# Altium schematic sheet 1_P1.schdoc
size 309 x 223 mm; Symbol: Sheet-Symbol_A4; Device: Sheet-Symbol_A4; Company: 嘉立创EDA; Version: V1.0; Page Size: A4; @Project Name: 辉光管_2024.2.16; @Page Count: 1; @Update Date: 2024-05-18; @Create Date: 2024-05-18; @Schematic Name: Schematic5; @Page No: 1; @Page Name: P1
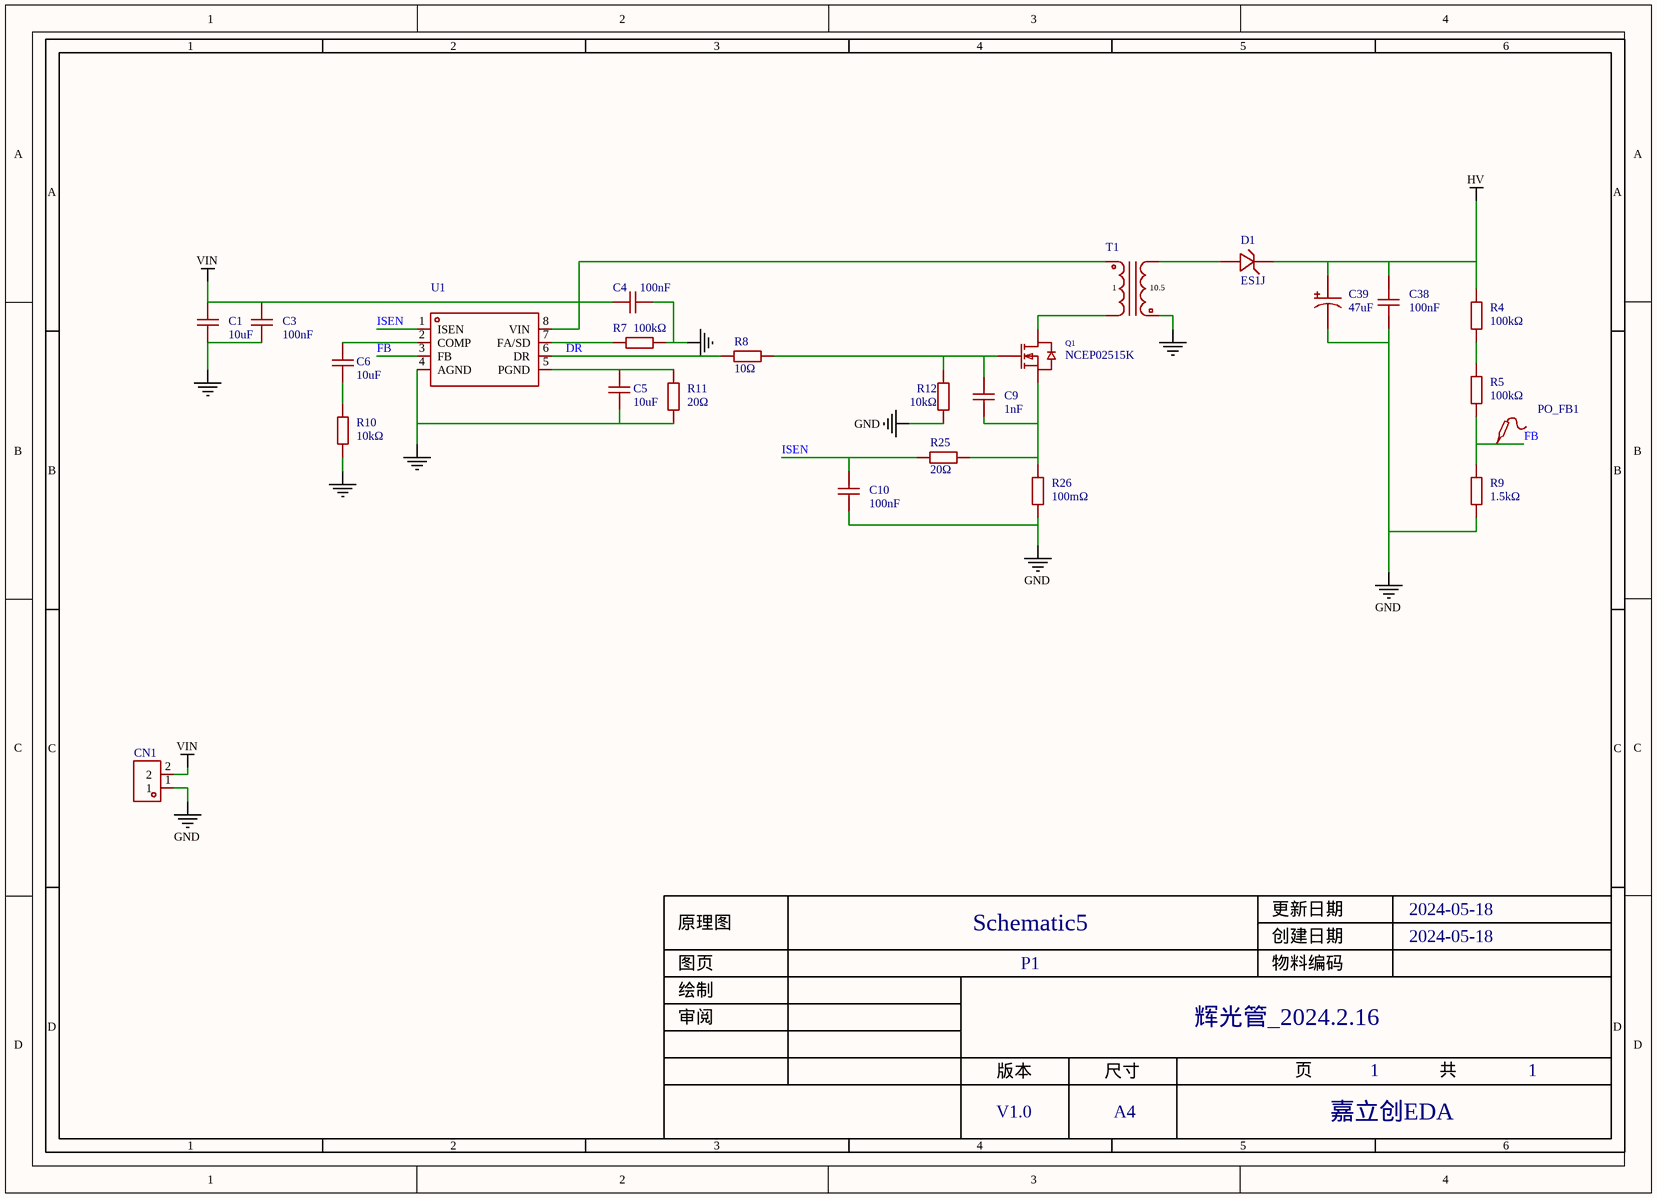
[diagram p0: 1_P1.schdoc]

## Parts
C1  10uF  [C0805]  (value not drawn)
C3  100nF  [C0603]  (value not drawn)
C4  100nF  [C0603]  (value not drawn)
C5  10uF  [C0805]  (value not drawn)
C6  10uF  [C0805]  (value not drawn)
C9  1nF  [C0603]  (value not drawn)
C10  100nF  [C0603]  (value not drawn)
C38  100nF  [C1206]  (value not drawn)
C39  47uF  [CAP-TH_BD12.5-P5.00-D0.6-FD]  (value not drawn)
CN1  ZX-XH2.54-2PZZ  [CONN-TH_2P-P2.50_HX25003-2A]  (value not drawn)
D1  ES1J  [SMA_L4.4-W2.8-LS5.4-RD]  (value not drawn)
PO_FB1  Test-Point  [Test-Point-0.5mm]  (value not drawn)
Q1  NCEP02515K  [TO-252-3_L6.6-W6.1-P4.58-LS10.1-BR-2]  (value not drawn)
R4  100kΩ  [R1206]  (value not drawn)
R5  100kΩ  [R1206]  (value not drawn)
R7  100kΩ  [R0603]  (value not drawn)
R8  10Ω  [R0603]  (value not drawn)
R9  1.5kΩ  [R0805]  (value not drawn)
R10  10kΩ  [R0603]  (value not drawn)
R11  20Ω  [R0603]  (value not drawn)
R12  10kΩ  [R0603]  (value not drawn)
R25  20Ω  [R0603]  (value not drawn)
R26  100mΩ  [R1206]  (value not drawn)
T1  TTRN-060S-013-T  [TTRN-060S-013]  (value not drawn)
U1  SiLM6478-AQ/Boost升压芯片  [MSOP-8_L3.0-W3.0-P0.65-LS4.9-TL]  (value not drawn)

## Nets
GND: C1.1 C3.1 C4.1 C5.1 C10.1 C38.1 C39.2 CN1.1 R7.1 R9.1 R10.1 R11.1 R12.1 R26.1 T1.3 U1.4(AGND)
HV: C38.2 C39.1 D1.1(C) R4.1
VIN: C1.2 C3.2 C4.2 CN1.2 T1.1 U1.8(VIN)
DR: R8.1 U1.6(DR)
FB: PO_FB1.1 R5.2 R9.2 U1.3(FB)
ISEN: C10.2 R25.1 U1.1(ISEN)
NetC5_2: C5.2 R11.2 U1.5(PGND)
NetC6_1: C6.1 R10.2
NetC6_2: C6.2 U1.2(COMP)
NetC9_1: C9.1 Q1.3(S) R25.2 R26.2
NetC9_2: C9.2 Q1.1(G) R8.2 R12.2
NetD1_2: D1.2(A) T1.2
NetQ1_2: Q1.2(D) T1.5
NetR4_2: R4.2 R5.1
NetR7_2: R7.2 U1.7(FA/SD)

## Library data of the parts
C1 C5 C6 = 0805X106K250NT: 容值:10uF;精度:±10%;额定电压:25V;材质(温度系数):X5R;; Manufacturer: FH(风华); Add into BOM: yes; Tolerance: ±10%; Voltage Rated: 25V; Temperature Coefficient: X5R
C3 C4 C10 = 0603B104K500NT: 容值:100nF;精度:±10%;额定电压:50V;材质(温度系数):X7R;; Manufacturer: FH(风华); Add into BOM: yes; Tolerance: ±10%; Voltage Rated: 50V; Temperature Coefficient: X7R
C9 = CC0603KRX7R9BB102: 容值:1nF;精度:±10%;额定电压:50V;材质(温度系数):X7R;; Manufacturer: YAGEO(国巨); Add into BOM: yes; Tolerance: ±10%; Voltage Rated: 50V; Temperature Coefficient: X7R
C38 = 1206B104K251NT_C2909525: 容值:100nF;精度:±10%;额定电压:250V;材质(温度系数):X7R;; Manufacturer: FH(风华); Add into BOM: yes; Tolerance: ±10%; Voltage Rated: 250V; Temperature Coefficient: X7R
C39 = EGS2EM470W16OT: 容值:47uF;精度:±20%;额定电压:250V;纹波电流:-;等效串联电阻:-;; Manufacturer: AISHI(艾华集团); Add into BOM: yes; Tolerance: ±20%; Rated Voltage: 250V; φD: 12.5mm; L: 16mm; Lifetime @ Temp: 6000hrs@105℃
CN1 = ZX-XH2.54-2PZZ: 插针结构:1x2P;间距:2.54mm;安装方式:直插;参考系列:XH;总PIN数:2P;排数:1;每排PIN数:2;行距:-;额定电流:3A;触头材质:黄铜;触头镀层:锡;工作温度范围:-25℃~+85℃;; Manufacturer: Megastar(兆星); Add into BOM: yes; Pins Structure: 1x2P; Pitch: 2.54mm; Reference Series: XH; Number of PINs Per Row: 2; Current Rating (Max): 3A
D1 = ES1J_C412438: 二极管配置:独立式;正向压降(Vf):1.7V@1A;直流反向耐压(Vr):600V;平均整流电流(Io):1A;反向恢复时间(trr):35ns;; Manufacturer: MDD; Symbol: ES1JG_C412438; Add into BOM: yes; Diode Configuration: 独立式; Reverse Voltage (Vr): 600V; Average Rectified Current (Io): 1A; Reverse Leakage Current: 5uA@600V; Reverse Recovery Time (trr): 35ns
PO_FB1 = Test-Point: Test Point 测试点; Add into BOM: yes
Q1 = NCEP02515K: 类型:N沟道;漏源电压(Vdss):250V;连续漏极电流(Id):15A;功率(Pd):140W;导通电阻(RDS(on)@Vgs,Id):200mΩ@10V,15A;阈值电压(Vgs(th)@Id):3.5V@250uA;; Manufacturer: NCE(无锡新洁能); Add into BOM: yes; Type: N沟道; Drain Source Voltage (Vdss): 250V; Power Dissipation (Pd): 140W; Total Gate Charge (Qg@Vgs): 8.9nC@10V; Input Capacitance (Ciss@Vds): 475pF@125V; Reverse Transfer Capacitance (Crss@Vds): 1.2pF@125V
R4 R5 = 1206W4F1003T5E: 电阻类型:厚膜电阻;阻值:100kΩ;精度:±1%;功率:250mW;最大工作电压:200V;温度系数:±100ppm/℃;; Manufacturer: UNI-ROYAL(厚声); Add into BOM: yes; Tolerance: ±1%; Power(Watts): 250mW; Overload Voltage (Max): 200V
R7 = 0603WAF1003T5E: 电阻类型:厚膜电阻;阻值:100kΩ;精度:±1%;功率:100mW;最大工作电压:75V;温度系数:±100ppm/℃;; Manufacturer: UNI-ROYAL(厚声); Add into BOM: yes; Tolerance: ±1%; Power(Watts): 100mW; Overload Voltage (Max): 75V
R8 = 0603WAF100JT5E: 电阻类型:厚膜电阻;阻值:10Ω;精度:±1%;功率:100mW;最大工作电压:75V;温度系数:±400ppm/℃;; Manufacturer: UNI-ROYAL(厚声); Add into BOM: yes; Tolerance: ±1%; Power(Watts): 100mW; Overload Voltage (Max): 75V
R9 = 0805W8F1501T5E: 电阻类型:厚膜电阻;阻值:1.5kΩ;精度:±1%;功率:125mW;最大工作电压:150V;温度系数:±100ppm/℃;; Manufacturer: UNI-ROYAL(厚声); Add into BOM: yes; Tolerance: ±1%; Power(Watts): 125mW; Overload Voltage (Max): 150V
R10 R12 = 0603WAF1002T5E: 电阻类型:厚膜电阻;阻值:10kΩ;精度:±1%;功率:100mW;; Manufacturer: UNI-ROYAL(厚声); Add into BOM: yes; Tolerance: ±1%; Power(Watts): 100mW; Temperature Coefficient: ±100ppm/℃; Overload Voltage (Max): 75V
R11 R25 = 0603WAF200JT5E: 电阻类型:厚膜电阻;阻值:20Ω;精度:±1%;功率:100mW;最大工作电压:75V;温度系数:±100ppm/℃;; Manufacturer: UNI-ROYAL(厚声); Add into BOM: yes; Tolerance: ±1%; Power(Watts): 100mW; Overload Voltage (Max): 75V
R26 = 1206W4F100LT5E: 电阻类型:厚膜电阻;阻值:100mΩ;精度:±1%;功率:250mW;最大工作电压:200V;温度系数:±800ppm/℃;; Manufacturer: UNI-ROYAL(厚声); Add into BOM: yes; Tolerance: ±1%; Power(Watts): 250mW; Overload Voltage (Max): 200V
T1 = TTRN-060S-013-T: Pin Type: IN; Add into BOM: yes
U1 = SiLM6478-AQ/Boost升压芯片: Add into BOM: yes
